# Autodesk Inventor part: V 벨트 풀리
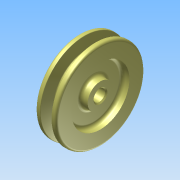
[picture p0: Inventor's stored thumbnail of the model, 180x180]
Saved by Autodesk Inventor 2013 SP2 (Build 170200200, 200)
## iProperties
Created: 2025-10
Part Number: V 벨트 풀리
Material: Generic
Document SubType Name: Modeling
Designer: 601
Density: 1 g/cm^3
Author: 601
변환 표준: STEP AP214IS
전처리기: Build: 200, Release: 2013 SP2 Update 6 - Date: Thu 07/17/2014
전송 단위: 밀리미터
불확실성: 0.01
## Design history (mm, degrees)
node "V 벨트 풀리1"
node "솔리드1"
node "기준1"
